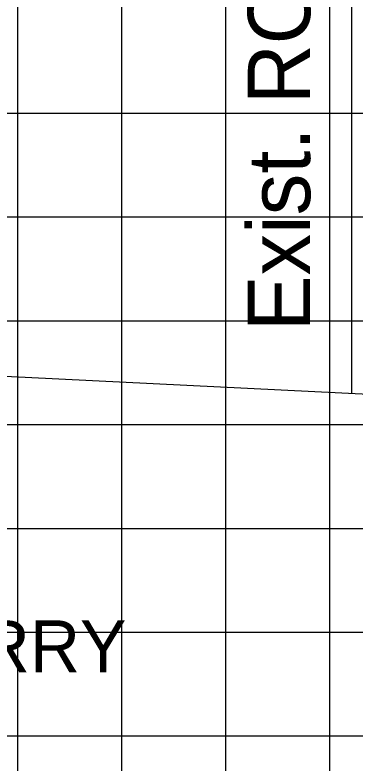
# Model space of a CAD drawing. Extents: x 859352 to 859522, y 366268 to 366378.
# Drawn here: x 859464.1 to 859467.37, y 366283.98 to 366291.18 of the extents above; entities that cross this region are included whole.
import ezdxf

# ---------------------------------------------------------------- set-up
doc = ezdxf.new("R2010")
doc.units = 0
for name, color, linetype in [('D_Text_Monospaced', 7, 'Continuous'), ('E_ROW_Line', 7, 'Continuous'), ('MAJOR', 7, 'Continuous'), ('MINOR', 7, 'Continuous'), ('S_Roadway_Centerline', 7, 'Continuous')]:
    doc.layers.add(name, color=color, linetype=linetype)

msp = doc.modelspace()

# ---------------------------------------------------------------- linework, layer by layer
at = {"layer": 'E_ROW_Line'}
msp.add_line((859467.3417, 366287.5365), (859467.3417, 366297.5365), dxfattribs=at)
at = {"layer": 'MAJOR'}
for p, q in [((859465.1294, 366277.2365), (859465.1294, 366297.2365)), ((859365.1294, 366287.2365), (859505.1294, 366287.2365))]:
    msp.add_line(p, q, dxfattribs=at)
at = {"layer": 'MINOR'}
for p, q in [((859464.1294, 366277.2365), (859464.1294, 366297.2365)), ((859466.1294, 366277.2365), (859466.1294, 366297.2365)), ((859467.1294, 366277.2365), (859467.1294, 366297.2365)), ((859365.1294, 366290.2365), (859505.1294, 366290.2365)), ((859365.1294, 366289.2365), (859505.1294, 366289.2365)), ((859365.1294, 366288.2365), (859505.1294, 366288.2365)), ((859365.1294, 366286.2365), (859505.1294, 366286.2365)), ((859365.1294, 366285.2365), (859505.1294, 366285.2365)), ((859365.1294, 366284.2365), (859505.1294, 366284.2365))]:
    msp.add_line(p, q, dxfattribs=at)
at = {"layer": 'S_Roadway_Centerline'}
msp.add_lwpolyline([(859406.4476, 366287.9895), (859414.4977, 366288.475), (859414.8625, 366288.5159), (859418.0236, 366288.4368), (859419.4455, 366288.4025), (859419.7817, 366288.3886), (859419.8076, 366288.3661), (859420.2709, 366287.8535), (859420.5704, 366287.8666), (859422.855, 366287.9873), (859424.3922, 366288.0745), (859424.9968, 366288.1014), (859426.1169, 366288.1231), (859435.8076, 366288.308), (859445.1105, 366288.0711), (859445.5475, 366288.0605), (859452.1937, 366287.4843), (859452.255, 366287.4811), (859453.1692, 366287.4751), (859453.8289, 366288.0766), (859453.8668, 366288.1002), (859456.7345, 366287.9871), (859463.9377, 366287.7043), (859477.1652, 366287.052)], dxfattribs=at)

# ---------------------------------------------------------------- texts
at = {"layer": 'D_Text_Monospaced'}
msp.add_text('EXIST. 5" CHERRY', height=0.49998, dxfattribs=at).set_placement((859459.2519, 366284.8495))
at = {"layer": 'E_ROW_Line'}
msp.add_text('Exist. ROW Line', height=0.6, rotation=90, dxfattribs=at).set_placement((859466.9417, 366288.1365))

doc.saveas('drawing.dxf')
